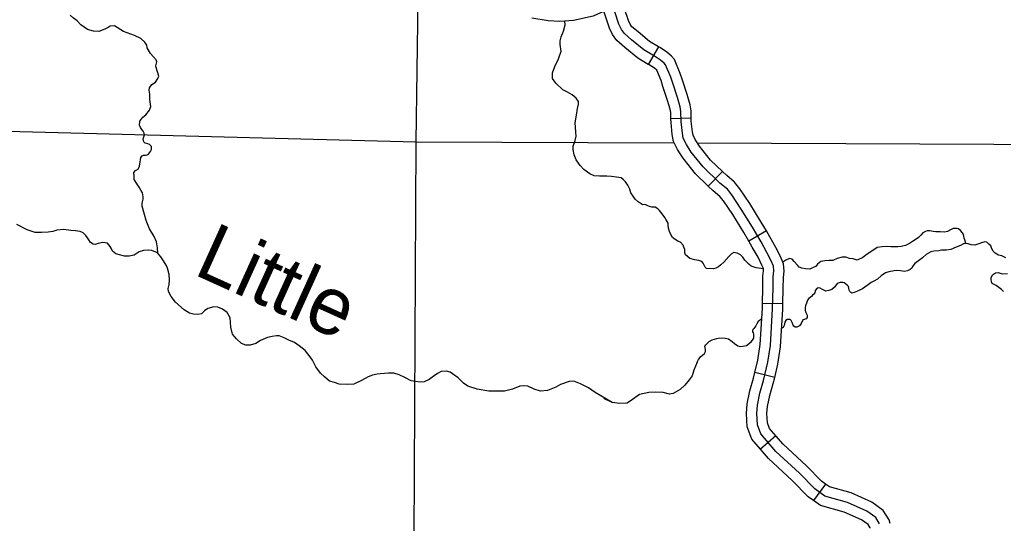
# Model space of a CAD drawing. Extents: x 1373862 to 1377080, y 1164775 to 1170415.
# Drawn here: x 1375152.2 to 1375269.5, y 1168654.6 to 1168714.6 of the extents above; entities that cross this region are included whole.
import ezdxf

# ---------------------------------------------------------------- set-up
doc = ezdxf.new("R2010")
doc.units = 0
for name, color, linetype in [('Level 32', 7, 'Continuous'), ('Level 35', 7, 'Continuous'), ('Level 45', 7, 'Continuous'), ('Level 5', 7, 'Continuous')]:
    doc.layers.add(name, color=color, linetype=linetype)

msp = doc.modelspace()

# ---------------------------------------------------------------- linework, layer by layer
at = {"layer": 'Level 32'}
for p, q in [((1375228.39, 1168711.35), (1375227.15, 1168709.26)), ((1375232.28, 1168702.83), (1375229.86, 1168702.76)), ((1375236, 1168696.5), (1375234.31, 1168694.75)), ((1375241.25, 1168689.42), (1375239.15, 1168688.18)), ((1375243.21, 1168680.7), (1375240.78, 1168680.75)), ((1375242.24, 1168671.95), (1375239.88, 1168672.53)), ((1375242.37, 1168665), (1375240.53, 1168663.41)), ((1375248.29, 1168659.24), (1375246.86, 1168657.27))]:
    msp.add_line(p, q, dxfattribs=at)
for points in [[(1375228.39, 1168711.35), (1375227.32, 1168711.99), (1375225.94, 1168713.13), (1375225.21, 1168713.75), (1375225, 1168714.05), (1375224.79, 1168714.5), (1375224.31, 1168715.89), (1375224.07, 1168716.73)], [(1375222.26, 1168715.77), (1375220.57, 1168715.02), (1375218.23, 1168714.47), (1375216.59, 1168714.36), (1375215.2, 1168714.45), (1375213.25, 1168714.77)], [(1375227.15, 1168709.26), (1375225.92, 1168709.99), (1375224.38, 1168711.27), (1375223.41, 1168712.1), (1375222.89, 1168712.81), (1375222.53, 1168713.59), (1375221.85, 1168715.59)], [(1375232.28, 1168702.83), (1375232.26, 1168703.72), (1375232.16, 1168704.45), (1375231.79, 1168705.68), (1375231.23, 1168707.37), (1375230.98, 1168708.17), (1375230.27, 1168709.84), (1375229.94, 1168710.25), (1375229.35, 1168710.76), (1375228.53, 1168711.27), (1375228.39, 1168711.35)], [(1375229.86, 1168702.76), (1375229.83, 1168703.53), (1375229.78, 1168703.93), (1375229.47, 1168704.94), (1375228.91, 1168706.62), (1375228.69, 1168707.34), (1375228.17, 1168708.56), (1375227.9, 1168708.8), (1375227.27, 1168709.19), (1375227.15, 1168709.26)], [(1375234.31, 1168694.75), (1375232.8, 1168696.21), (1375231.31, 1168698.07), (1375230.64, 1168699.11), (1375230.17, 1168700.07), (1375230.02, 1168700.89), (1375229.87, 1168702.32), (1375229.86, 1168702.76)], [(1375236, 1168696.5), (1375234.6, 1168697.85), (1375233.28, 1168699.5), (1375232.76, 1168700.3), (1375232.5, 1168700.83), (1375232.43, 1168701.23), (1375232.29, 1168702.48), (1375232.28, 1168702.83)], [(1375241.25, 1168689.42), (1375240.63, 1168690.47), (1375239.27, 1168692.68), (1375238.09, 1168694.41), (1375237.46, 1168695.22), (1375236.51, 1168696), (1375236, 1168696.5)], [(1375239.15, 1168688.18), (1375238.55, 1168689.22), (1375237.23, 1168691.36), (1375236.13, 1168692.98), (1375235.71, 1168693.51), (1375234.89, 1168694.18), (1375234.31, 1168694.75)], [(1375243.21, 1168680.7), (1375243.26, 1168682.6), (1375243.27, 1168683.87), (1375243.35, 1168684.61), (1375243.29, 1168685.47), (1375242.93, 1168686.35), (1375242.39, 1168687.42), (1375241.67, 1168688.71), (1375241.25, 1168689.42)], [(1375240.78, 1168680.75), (1375240.83, 1168682.64), (1375240.84, 1168684.01), (1375240.91, 1168684.65), (1375240.9, 1168684.91), (1375240.72, 1168685.34), (1375240.25, 1168686.28), (1375239.56, 1168687.49), (1375239.15, 1168688.18)], [(1375239.88, 1168672.53), (1375240.24, 1168674), (1375240.52, 1168675.86), (1375240.77, 1168680.19), (1375240.78, 1168680.75)], [(1375242.24, 1168671.95), (1375242.63, 1168673.53), (1375242.94, 1168675.6), (1375243.2, 1168680.09), (1375243.21, 1168680.7)], [(1375240.53, 1168663.41), (1375239.5, 1168664.6), (1375238.97, 1168666.05), (1375238.88, 1168667.66), (1375238.96, 1168668.79), (1375239.28, 1168670.36), (1375239.72, 1168671.87), (1375239.88, 1168672.53)], [(1375242.37, 1168665), (1375241.63, 1168665.86), (1375241.37, 1168666.55), (1375241.31, 1168667.64), (1375241.37, 1168668.46), (1375241.64, 1168669.78), (1375242.06, 1168671.24), (1375242.24, 1168671.95)], [(1375248.29, 1168659.24), (1375247.83, 1168659.57), (1375246.04, 1168661.4), (1375243.25, 1168663.98), (1375242.37, 1168665)], [(1375246.86, 1168657.27), (1375246.23, 1168657.73), (1375244.34, 1168659.66), (1375241.5, 1168662.29), (1375240.53, 1168663.41)], [(1375256, 1168654.55), (1375255.9, 1168654.97), (1375255.19, 1168656.1), (1375253.81, 1168657.07), (1375251.35, 1168658.17), (1375248.76, 1168658.89), (1375248.29, 1168659.24)], [(1375253.64, 1168653.98), (1375253.63, 1168654.02), (1375253.39, 1168654.4), (1375252.61, 1168654.95), (1375250.52, 1168655.88), (1375247.69, 1168656.67), (1375246.86, 1168657.27)]]:
    msp.add_lwpolyline(points, dxfattribs=at)
at = {"layer": 'Level 35'}
for points in [[(1375163.47, 1168713.84), (1375162.96, 1168713.82), (1375162.73, 1168713.67), (1375162.35, 1168713.44), (1375161.63, 1168713.18), (1375160.98, 1168713.2), (1375160.26, 1168713.41), (1375159.48, 1168713.98), (1375159.02, 1168714.46), (1375158.61, 1168714.78), (1375158.21, 1168715.12)], [(1375216.75, 1168710.83), (1375216.64, 1168711.62), (1375216.66, 1168712.06), (1375216.75, 1168712.53), (1375217.06, 1168713.23), (1375217.23, 1168713.97), (1375217.22, 1168714.4)], [(1375168.77, 1168707.86), (1375168.44, 1168708.89), (1375168.42, 1168709.1), (1375168.52, 1168709.57), (1375168.44, 1168709.82), (1375168.1, 1168710.2), (1375167.76, 1168710.56), (1375167.4, 1168711.24), (1375167.36, 1168711.56), (1375167.11, 1168711.92), (1375166.64, 1168712.36), (1375165.86, 1168712.72), (1375164.55, 1168713.19), (1375163.47, 1168713.84)], [(1375222.22, 1168695.95), (1375221.35, 1168695.93), (1375220.7, 1168695.97), (1375220.17, 1168696.2), (1375219.49, 1168696.73), (1375219.03, 1168697.2), (1375218.54, 1168697.88), (1375218.31, 1168698.47), (1375218.2, 1168699.1), (1375218.2, 1168699.52), (1375218.42, 1168700.18), (1375218.56, 1168700.69), (1375218.5, 1168701.19), (1375218.46, 1168701.79), (1375218.42, 1168702.29), (1375218.58, 1168703.22), (1375218.71, 1168704.01), (1375218.82, 1168704.51), (1375218.82, 1168704.82), (1375218.56, 1168705.23), (1375218.08, 1168705.61), (1375217.51, 1168705.94), (1375216.98, 1168706.22), (1375216.13, 1168707), (1375215.75, 1168707.59), (1375215.75, 1168708.25), (1375216.03, 1168709.01), (1375216.45, 1168709.9), (1375216.75, 1168710.83)], [(1375167.71, 1168705.09), (1375167.68, 1168705.72), (1375167.63, 1168706.19), (1375167.65, 1168706.46), (1375167.95, 1168706.86), (1375168.37, 1168707.12), (1375168.67, 1168707.56), (1375168.77, 1168707.86)], [(1375166.91, 1168700.4), (1375167.05, 1168700.87), (1375167.04, 1168701.05), (1375166.9, 1168701.29), (1375166.76, 1168701.49), (1375166.57, 1168701.72), (1375166.46, 1168702), (1375166.5, 1168702.47), (1375166.86, 1168702.95), (1375167.21, 1168703.26), (1375167.66, 1168703.81), (1375167.8, 1168704.23), (1375167.71, 1168705.09)], [(1375166.54, 1168697.64), (1375166.57, 1168697.88), (1375166.61, 1168698.14), (1375166.78, 1168698.35), (1375166.96, 1168698.43), (1375167.18, 1168698.44), (1375167.39, 1168698.48), (1375167.56, 1168698.57), (1375167.77, 1168698.86), (1375167.88, 1168699.11), (1375167.89, 1168699.31), (1375167.88, 1168699.46), (1375167.79, 1168699.6), (1375167.65, 1168699.71), (1375167.46, 1168699.8), (1375167.13, 1168699.88), (1375166.99, 1168700.02), (1375166.93, 1168700.17), (1375166.91, 1168700.4)], [(1375168.67, 1168686.77), (1375168.61, 1168687.4), (1375168.51, 1168688.12), (1375168.23, 1168688.73), (1375167.64, 1168689.67), (1375167.28, 1168690.66), (1375167.07, 1168691.36), (1375166.78, 1168692.37), (1375166.8, 1168692.73), (1375166.9, 1168693.18), (1375166.9, 1168693.49), (1375166.84, 1168693.96), (1375166.63, 1168694.27), (1375166.42, 1168694.63), (1375166.12, 1168695.1), (1375165.85, 1168695.52), (1375165.82, 1168695.92), (1375165.8, 1168696.37), (1375165.97, 1168696.6), (1375166.31, 1168696.77), (1375166.48, 1168697.11), (1375166.54, 1168697.64)], [(1375226.44, 1168692.55), (1375225.96, 1168692.86), (1375225.58, 1168693.18), (1375225.35, 1168693.56), (1375225.09, 1168693.96), (1375224.94, 1168694.37), (1375224.71, 1168694.87), (1375224.44, 1168695.25), (1375224.16, 1168695.53), (1375223.91, 1168695.74), (1375223.36, 1168695.82), (1375222.79, 1168695.91), (1375222.22, 1168695.95)], [(1375232.12, 1168686.13), (1375231.59, 1168686.55), (1375231.51, 1168686.78), (1375231.51, 1168687.18), (1375231.4, 1168687.46), (1375231.32, 1168687.69), (1375231.02, 1168688.05), (1375230.69, 1168688.18), (1375230.37, 1168688.37), (1375230.03, 1168688.64), (1375229.9, 1168688.92), (1375229.67, 1168689.32), (1375229.59, 1168689.74), (1375229.52, 1168690.1), (1375229.52, 1168690.35), (1375229.31, 1168690.73), (1375229.12, 1168691.01), (1375228.83, 1168691.43), (1375228.51, 1168691.86), (1375228.3, 1168692.05), (1375227.96, 1168692.24), (1375227.58, 1168692.24), (1375227.31, 1168692.32), (1375227.09, 1168692.4), (1375226.88, 1168692.53), (1375226.69, 1168692.55), (1375226.5, 1168692.53), (1375226.44, 1168692.55)], [(1375157.44, 1168689.58), (1375156.59, 1168689.48), (1375156.12, 1168689.35), (1375155.57, 1168689.25), (1375154.79, 1168689.23), (1375154.03, 1168689.23), (1375153.08, 1168689.54), (1375151.85, 1168690.18)], [(1375168.61, 1168686.81), (1375167.94, 1168687.06), (1375167.52, 1168687.11), (1375166.94, 1168687.09), (1375166.44, 1168686.92), (1375165.82, 1168686.51), (1375165.25, 1168686.39), (1375164.68, 1168686.41), (1375164.09, 1168686.54), (1375163.63, 1168686.66), (1375163.23, 1168687), (1375163.1, 1168687.36), (1375162.97, 1168687.57), (1375162.63, 1168687.93), (1375162.09, 1168688.02), (1375161.54, 1168687.91), (1375161.16, 1168687.8), (1375160.92, 1168687.83), (1375160.61, 1168688.04), (1375160.42, 1168688.35), (1375160.25, 1168688.59), (1375160.08, 1168688.86), (1375159.74, 1168689.18), (1375159.38, 1168689.35), (1375158.85, 1168689.41), (1375158.28, 1168689.47), (1375157.44, 1168689.58)], [(1375265.03, 1168687.92), (1375264.9, 1168688.34), (1375264.84, 1168688.56), (1375264.79, 1168688.77), (1375264.76, 1168688.99), (1375264.64, 1168689.17), (1375264.41, 1168689.46), (1375264.17, 1168689.67), (1375264.01, 1168689.69), (1375263.75, 1168689.69), (1375263.53, 1168689.69), (1375263.21, 1168689.54), (1375262.84, 1168689.35), (1375262.49, 1168689.27), (1375261.96, 1168689.29), (1375261.48, 1168689.31), (1375261.16, 1168689.35), (1375260.75, 1168689.41), (1375260.42, 1168689.41), (1375260.23, 1168689.35), (1375259.91, 1168689.17), (1375259.66, 1168688.9), (1375259.4, 1168688.63), (1375259.11, 1168688.41), (1375258.66, 1168688.16), (1375258.3, 1168687.92), (1375257.84, 1168687.65), (1375257.34, 1168687.54), (1375256.93, 1168687.53)], [(1375256.93, 1168687.53), (1375256.09, 1168687.51), (1375255.57, 1168687.55), (1375255.04, 1168687.53), (1375254.45, 1168687.44), (1375253.81, 1168687), (1375253.28, 1168686.62), (1375252.76, 1168686.24), (1375252.06, 1168685.94), (1375251.61, 1168686.07), (1375251.15, 1168686.13), (1375250.71, 1168686.26), (1375250.71, 1168686.26), (1375250.3, 1168686.28), (1375249.69, 1168686.11), (1375249.16, 1168685.9), (1375248.7, 1168685.88), (1375248.21, 1168685.84), (1375247.73, 1168685.75), (1375247.35, 1168685.45), (1375247.14, 1168685.18), (1375247.12, 1168685.16)], [(1375265.69, 1168687.76), (1375265.33, 1168687.86), (1375265.03, 1168687.92), (1375264.78, 1168687.86), (1375264.4, 1168687.65), (1375263.89, 1168687.48), (1375263.24, 1168687.18), (1375262.75, 1168687.12), (1375262.12, 1168687.12), (1375261.82, 1168687.05), (1375261.23, 1168687.01), (1375260.87, 1168686.91), (1375260.3, 1168686.61), (1375259.88, 1168686.19), (1375259.57, 1168685.95)], [(1375268.94, 1168686.53), (1375268.54, 1168686.74), (1375268.28, 1168687), (1375268.16, 1168687.27), (1375268.03, 1168687.63), (1375267.8, 1168687.82), (1375267.55, 1168688.05), (1375267.31, 1168688.1), (1375266.89, 1168687.99), (1375266.57, 1168687.88), (1375266.13, 1168687.69), (1375265.69, 1168687.76)], [(1375196.15, 1168672.47), (1375195.2, 1168672.37), (1375194.82, 1168672.32), (1375194.25, 1168672.2), (1375193.74, 1168672.03), (1375192.94, 1168671.56), (1375192.03, 1168671.16), (1375191.29, 1168671.12), (1375190.3, 1168671.14), (1375189.73, 1168671.35), (1375189.12, 1168671.5), (1375188.53, 1168672.01), (1375188.06, 1168672.45), (1375187.51, 1168673.19), (1375187.11, 1168674.02), (1375186.71, 1168674.54), (1375186.24, 1168675.14), (1375185.53, 1168675.71), (1375184.96, 1168676.11), (1375184.3, 1168676.38), (1375183.73, 1168676.66), (1375183.14, 1168676.89), (1375182.81, 1168676.89), (1375182.28, 1168676.83), (1375181.73, 1168676.7), (1375180.91, 1168676.36), (1375180.33, 1168675.98), (1375179.66, 1168675.77), (1375179.17, 1168675.77), (1375178.62, 1168675.98), (1375178.03, 1168676.55), (1375177.57, 1168677.1), (1375177.38, 1168677.93), (1375177.33, 1168678.48), (1375177.27, 1168679.03), (1375176.93, 1168679.68), (1375176.36, 1168680.08), (1375175.81, 1168680.3), (1375175.35, 1168680.36), (1375174.61, 1168680.15), (1375174.23, 1168679.87), (1375173.87, 1168679.53), (1375173.43, 1168679.45), (1375172.9, 1168679.47), (1375172.43, 1168679.62), (1375171.8, 1168680), (1375170.76, 1168680.91), (1375170.24, 1168681.59), (1375169.92, 1168682.17), (1375169.88, 1168682.53), (1375170, 1168683.01), (1375170.05, 1168683.52), (1375170, 1168684.22), (1375169.81, 1168684.98), (1375169.63, 1168685.33), (1375169.31, 1168685.86), (1375169.02, 1168686.3), (1375168.61, 1168686.81)], [(1375240.9, 1168684.89), (1375240.04, 1168684.99), (1375239.43, 1168685.2), (1375239.15, 1168685.43), (1375238.67, 1168685.92), (1375238.44, 1168686.28), (1375238.14, 1168686.55), (1375237.76, 1168686.74), (1375237.36, 1168686.85), (1375237.1, 1168686.68), (1375236.77, 1168686.34), (1375236.17, 1168685.69), (1375235.82, 1168685.37), (1375235.52, 1168685.12), (1375235.2, 1168684.97), (1375234.95, 1168684.9), (1375234.1, 1168684.93), (1375233.96, 1168685.1), (1375233.7, 1168685.58), (1375233.53, 1168685.75), (1375233.2, 1168685.9), (1375232.71, 1168685.96), (1375232.12, 1168686.13)], [(1375247.12, 1168685.16), (1375246.76, 1168684.99), (1375246.42, 1168684.84), (1375245.91, 1168684.88), (1375245.49, 1168684.95), (1375245.15, 1168685.07), (1375244.96, 1168685.33), (1375244.58, 1168685.75), (1375244.33, 1168686.05), (1375244.01, 1168686.11), (1375243.57, 1168685.92), (1375243.2, 1168685.69)], [(1375269.81, 1168686.21), (1375269.34, 1168686.43), (1375268.94, 1168686.53)], [(1375259.57, 1168685.95), (1375258.94, 1168685.52), (1375258.69, 1168685.17), (1375258.58, 1168684.98), (1375258.38, 1168684.8), (1375258.1, 1168684.63), (1375257.71, 1168684.56), (1375257.24, 1168684.65), (1375256.73, 1168684.67), (1375256.49, 1168684.66), (1375255.85, 1168684.52), (1375255.44, 1168684.4), (1375254.95, 1168684.04), (1375254.51, 1168683.67), (1375254.06, 1168683.42), (1375253.76, 1168683.24), (1375253.28, 1168682.91), (1375252.7, 1168682.52), (1375252.11, 1168682.21), (1375251.7, 1168682.07)], [(1375269.55, 1168682.18), (1375269.28, 1168682.44), (1375268.66, 1168682.92), (1375268.18, 1168683.15), (1375268.09, 1168683.32), (1375268.07, 1168683.66), (1375268.07, 1168683.83), (1375268.2, 1168684.18), (1375268.58, 1168684.42), (1375268.88, 1168684.46), (1375269.36, 1168684.29), (1375270, 1168684.35)], [(1375247.3, 1168682.6), (1375247.08, 1168682.3), (1375247.02, 1168682.03), (1375246.91, 1168681.87), (1375246.75, 1168681.74), (1375246.61, 1168681.58), (1375246.33, 1168681.37), (1375246.14, 1168681.14), (1375246.07, 1168680.93)], [(1375251.7, 1168682.07), (1375251.43, 1168681.99), (1375251.32, 1168682.05), (1375251.2, 1168682.17), (1375251.13, 1168682.36), (1375251.09, 1168682.6), (1375251.03, 1168682.78), (1375250.89, 1168682.94), (1375250.69, 1168683.11), (1375250.51, 1168683.22), (1375250.35, 1168683.24), (1375250.03, 1168683.26), (1375249.7, 1168683.13), (1375249.37, 1168682.69), (1375249.04, 1168682.41), (1375248.69, 1168682.29), (1375248.32, 1168682.24), (1375247.94, 1168682.41), (1375247.66, 1168682.59), (1375247.48, 1168682.64), (1375247.3, 1168682.6)], [(1375246.07, 1168680.93), (1375245.9, 1168680.49), (1375245.87, 1168680.28), (1375245.87, 1168680.1), (1375245.86, 1168679.93), (1375245.94, 1168679.69), (1375246.1, 1168679.36), (1375246.12, 1168679.26), (1375246.11, 1168679.09), (1375246, 1168678.94), (1375245.74, 1168678.86), (1375245.59, 1168678.8), (1375245.54, 1168678.69), (1375245.49, 1168678.56), (1375245.41, 1168678.39), (1375245.19, 1168678.11), (1375244.89, 1168677.93)], [(1375240.7, 1168678.92), (1375240.27, 1168678.61), (1375240.1, 1168678.35), (1375239.98, 1168678.08), (1375239.76, 1168677.78), (1375239.68, 1168677.7)], [(1375244.89, 1168677.93), (1375244.67, 1168677.92), (1375244.53, 1168678.04), (1375244.44, 1168678.17), (1375244.32, 1168678.5), (1375244.19, 1168678.72), (1375244.08, 1168678.83), (1375243.92, 1168678.86), (1375243.72, 1168678.84), (1375243.58, 1168678.74), (1375243.44, 1168678.52), (1375243.36, 1168678.13), (1375243.23, 1168677.89), (1375243.07, 1168677.8)], [(1375233, 1168673.76), (1375233.16, 1168674.07), (1375233.42, 1168674.42), (1375233.64, 1168674.6), (1375233.86, 1168674.81), (1375234, 1168675.02), (1375233.98, 1168675.27), (1375233.96, 1168675.47), (1375233.91, 1168675.62), (1375234.04, 1168675.83), (1375234.21, 1168676.02), (1375234.44, 1168676.21), (1375234.76, 1168676.42), (1375235.34, 1168676.57), (1375235.71, 1168676.66), (1375236.32, 1168676.64), (1375236.71, 1168676.54), (1375236.74, 1168676.53)], [(1375236.74, 1168676.53), (1375237.17, 1168676.23), (1375237.44, 1168675.98), (1375237.83, 1168675.71), (1375238.15, 1168675.62), (1375238.87, 1168675.75), (1375239.42, 1168676.17), (1375239.59, 1168676.37), (1375239.75, 1168676.62), (1375239.76, 1168676.85), (1375239.73, 1168677.09), (1375239.7, 1168677.25), (1375239.63, 1168677.39), (1375239.63, 1168677.48), (1375239.68, 1168677.7)], [(1375233, 1168673.76), (1375232.58, 1168672.79), (1375232.41, 1168672.15), (1375232.03, 1168671.65), (1375231.5, 1168671.03), (1375230.96, 1168670.51), (1375230.13, 1168670.02), (1375229.69, 1168669.96), (1375228.95, 1168670.13), (1375228.02, 1168670.19), (1375227.22, 1168670.15), (1375226.12, 1168669.89), (1375225.29, 1168669.3), (1375224.62, 1168668.88), (1375223.75, 1168668.84), (1375222.84, 1168668.96), (1375221.87, 1168669.43)], [(1375210.95, 1168670.55), (1375210.01, 1168670.32), (1375208.13, 1168670.29), (1375206.73, 1168670.53), (1375205.63, 1168670.89), (1375205.11, 1168671.27), (1375204.47, 1168671.9), (1375203.82, 1168672.37), (1375203.52, 1168672.56), (1375203.08, 1168672.68), (1375202.47, 1168672.64), (1375202, 1168672.43), (1375201.62, 1168672.15), (1375201.03, 1168671.69), (1375200.44, 1168671.41), (1375199.95, 1168671.37), (1375198.89, 1168671.54), (1375198.11, 1168671.94), (1375197.44, 1168672.24), (1375196.82, 1168672.45), (1375196.15, 1168672.47)], [(1375222.84, 1168668.96), (1375220.84, 1168670.15), (1375220.02, 1168670.72), (1375219.09, 1168671.18), (1375218.28, 1168671.48), (1375217.73, 1168671.46), (1375216.7, 1168671.12), (1375216.15, 1168670.78), (1375215.14, 1168670.38), (1375214.29, 1168670.32), (1375213.53, 1168670.53), (1375212.81, 1168670.89), (1375212.33, 1168670.93), (1375211.82, 1168670.89), (1375210.95, 1168670.55)]]:
    msp.add_lwpolyline(points, dxfattribs=at)
at = {"layer": 'Level 45'}
for points in [[(1375241.73, 1168675.73), (1375241.99, 1168680.14), (1375242.04, 1168682.62), (1375242.06, 1168683.94), (1375242.13, 1168684.63), (1375242.09, 1168685.19), (1375241.82, 1168685.84), (1375241.32, 1168686.85), (1375240.61, 1168688.1), (1375239.59, 1168689.85), (1375238.25, 1168692.02), (1375237.11, 1168693.7), (1375236.59, 1168694.37), (1375235.7, 1168695.09), (1375233.7, 1168697.03), (1375232.29, 1168698.78), (1375231.7, 1168699.71), (1375231.33, 1168700.45), (1375231.23, 1168701.06), (1375231.08, 1168702.4), (1375231.05, 1168703.63), (1375230.97, 1168704.19), (1375230.63, 1168705.31), (1375230.07, 1168707), (1375229.84, 1168707.75), (1375229.22, 1168709.2), (1375229.06, 1168709.4), (1375228.63, 1168709.78), (1375227.9, 1168710.23), (1375226.62, 1168710.99), (1375225.16, 1168712.2), (1375224.31, 1168712.93), (1375223.95, 1168713.43), (1375223.66, 1168714.05), (1375223.15, 1168715.53)], [(1375254.76, 1168654.49), (1375254.29, 1168655.25), (1375253.21, 1168656.01), (1375250.93, 1168657.02), (1375248.22, 1168657.78), (1375247.03, 1168658.65), (1375245.19, 1168660.53), (1375242.37, 1168663.13), (1375240.57, 1168665.23), (1375240.17, 1168666.3), (1375240.1, 1168667.65), (1375240.17, 1168668.63), (1375240.46, 1168670.07), (1375240.89, 1168671.56), (1375241.43, 1168673.76), (1375241.73, 1168675.73)]]:
    msp.add_lwpolyline(points, dxfattribs=at)
at = {"layer": 'Level 5'}
for points in [[(1375199.68, 1168717.06), (1375199.42, 1168700.03)], [(1375127.79, 1168701.88), (1375199.42, 1168700.03)], [(1375199.42, 1168700.03), (1375199.07, 1168629.23)], [(1375199.42, 1168700.03), (1375230.2, 1168699.9)], [(1375233.02, 1168699.89), (1375286.08, 1168699.66)]]:
    msp.add_lwpolyline(points, dxfattribs=at)

# ---------------------------------------------------------------- texts
at = {"layer": 'Level 35'}
msp.add_text('Little', height=6.843, rotation=335.6376, dxfattribs=at).set_placement((1375172.76, 1168684.3))

doc.saveas('drawing.dxf')
